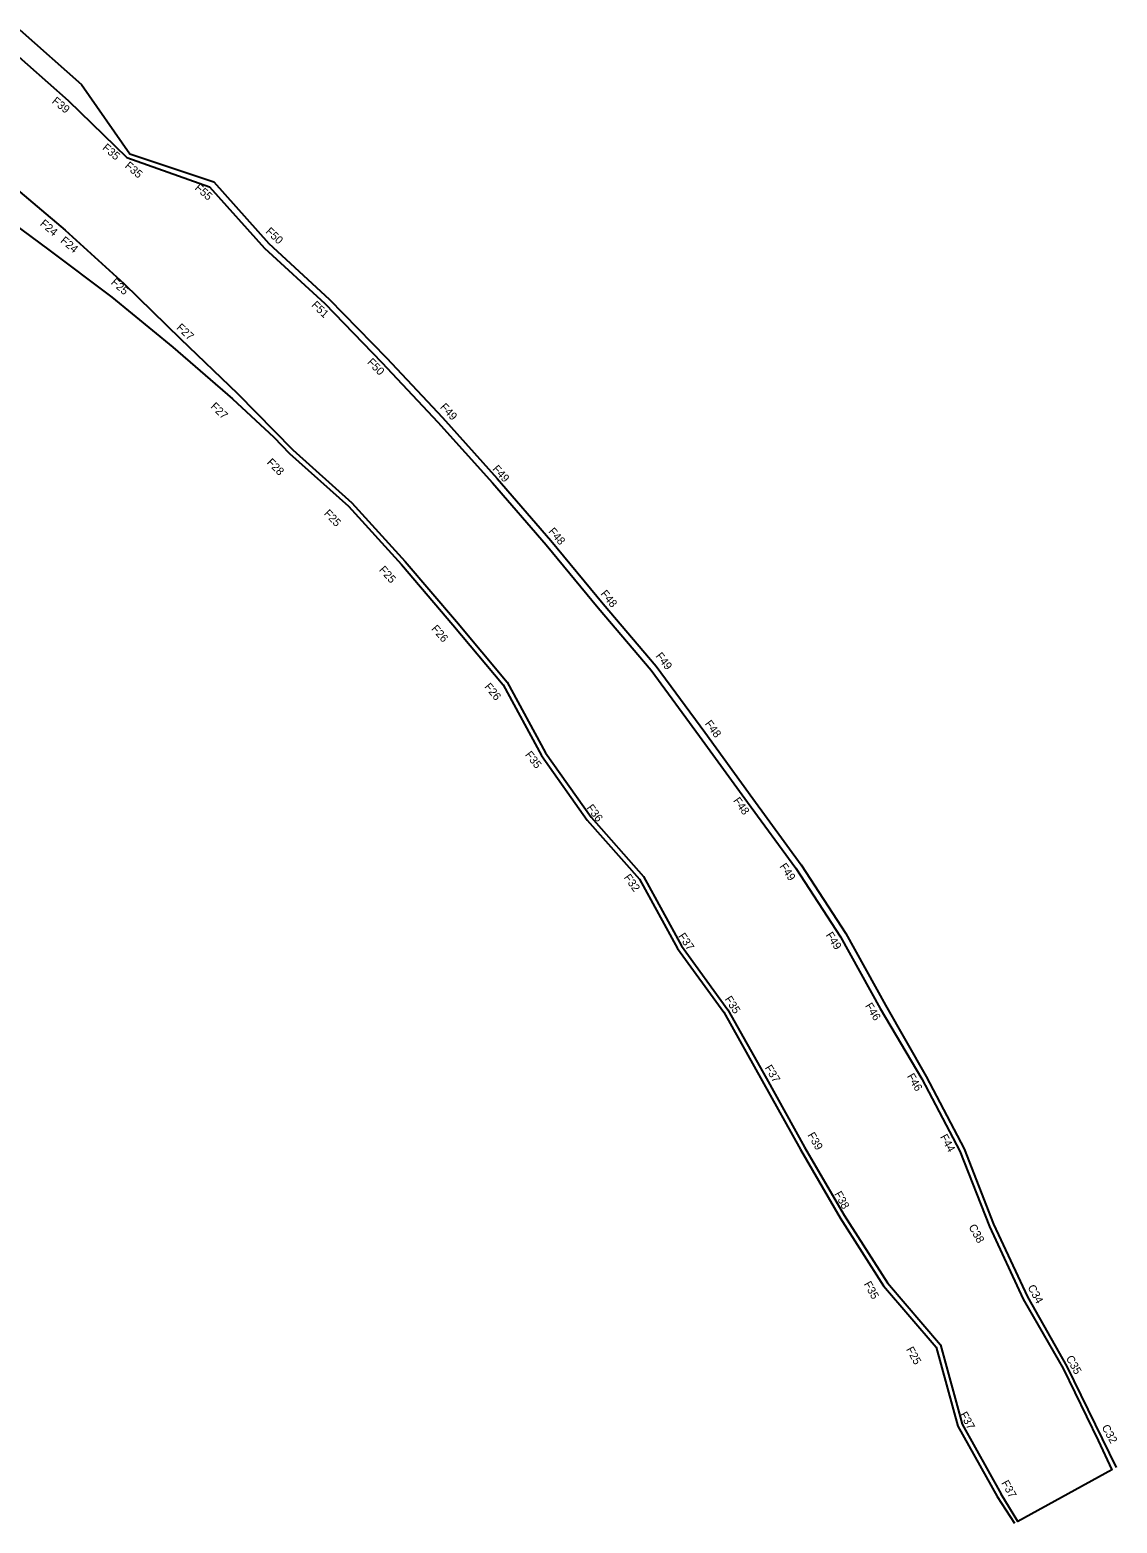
# Model space of a CAD drawing. Extents: x 2165700 to 2171741, y 206405 to 209505.
# Drawn here: x 2171061 to 2171741, y 206405 to 207338 of the extents above; entities that cross this region are included whole.
import ezdxf

# ---------------------------------------------------------------- set-up
doc = ezdxf.new("R2010")
doc.units = 0
for name, color, linetype in [('RD_PD_CstnLmt', 7, 'Continuous'), ('RD_PD_DR_ErosCtrl', 7, 'Continuous'), ('RD_PD_TX_CstnLmt', 7, 'Continuous')]:
    doc.layers.add(name, color=color, linetype=linetype)

msp = doc.modelspace()

# ---------------------------------------------------------------- linework, layer by layer
at = {"layer": 'RD_PD_CstnLmt'}
for points in [[(2171047.22, 207327.63), (2171085.37, 207293.75), (2171121.88, 207258.11), (2171173.6, 207239.9), (2171207.98, 207201.6), (2171245.57, 207166.91), (2171281.22, 207130.23), (2171316.21, 207092.95), (2171350.42, 207054.97), (2171383.88, 207016.35), (2171416.38, 206976.93), (2171449.56, 206938.03), (2171479.81, 206896.82), (2171509.79, 206855.45), (2171540.01, 206814.21), (2171567.81, 206771.31), (2171592.61, 206726.57), (2171618.69, 206682.69), (2171642.4, 206637.48), (2171660.83, 206590.52), (2171682.04, 206545.12), (2171706.99, 206501.78), (2171728.85, 206456.71), (2171737.27, 206438.53), (2171678.59, 206406.09), (2171668.26, 206423.23)], [(2171045.8, 207244.75), (2171083.48, 207212.71), (2171120.08, 207179.45), (2171155.48, 207144.95), (2171191.18, 207110.83), (2171225.73, 207075.56), (2171262.59, 207042.48), (2171295.84, 207005.89), (2171327.95, 206968.3), (2171359.65, 206930.39), (2171383.54, 206886.34), (2171412, 206846.17), (2171444.72, 206809.11), (2171468.47, 206765.68), (2171497.45, 206725.88), (2171521.54, 206682.93), (2171545.4, 206639.95), (2171570.09, 206597.48), (2171597.08, 206555.28), (2171630.29, 206516.51), (2171643.89, 206466.89), (2171668.26, 206423.23)]]:
    msp.add_lwpolyline(points, dxfattribs=at)
at = {"layer": 'RD_PD_DR_ErosCtrl'}
msp.add_line((2171665.64, 206421.77), (2171676.57, 206405.16), dxfattribs=at)
for points in [[(2171055.16, 207337.93), (2171093.53, 207303.87), (2171123.81, 207260.4), (2171176.25, 207242.9), (2171210.7, 207204.53), (2171248.36, 207169.78), (2171284.07, 207133.03), (2171319.12, 207095.69), (2171353.39, 207057.65), (2171386.91, 207018.96), (2171419.47, 206979.46), (2171452.71, 206940.5), (2171483.01, 206899.22), (2171513.05, 206857.77), (2171543.32, 206816.46), (2171571.17, 206773.48), (2171596.02, 206728.66), (2171621.28, 206684.2), (2171645.01, 206638.92), (2171663.46, 206591.98), (2171684.66, 206546.57), (2171684.66, 206546.57), (2171709.21, 206503.01), (2171739.96, 206439.85)], [(2171033.68, 207229.74), (2171073.21, 207200.56), (2171112.57, 207170.97), (2171150.67, 207139.76), (2171187.87, 207107.43), (2171187.87, 207107.43), (2171213.84, 207083.42)], [(2171213.84, 207083.42), (2171223.65, 207073.4), (2171260.47, 207040.35), (2171293.59, 207003.91), (2171325.66, 206966.37), (2171357.15, 206928.7), (2171380.99, 206884.76), (2171409.64, 206844.31), (2171442.25, 206807.38), (2171465.93, 206764.07), (2171494.92, 206724.26), (2171518.92, 206681.47), (2171542.79, 206638.47), (2171567.53, 206595.92), (2171594.67, 206553.49), (2171627.57, 206515.06), (2171641.1, 206465.75), (2171665.64, 206421.77)]]:
    msp.add_lwpolyline(points, dxfattribs=at)

# ---------------------------------------------------------------- texts
at = {"layer": 'RD_PD_TX_CstnLmt'}
for s, rotation, p in [('F39', 321.08168, (2171074.79, 207292.65)), ('F35', 319.77951, (2171106.27, 207263.6)), ('F35', 319.77951, (2171120.34, 207252.32)), ('F55', 318.47733, (2171164.09, 207238.66)), ('F24', 319.77951, (2171067.3, 207216.2)), ('F24', 319.77951, (2171080.07, 207205.6)), ('F50', 317.17515, (2171208.27, 207211.45)), ('F25', 318.47733, (2171111.7, 207179.61)), ('F51', 315.87298, (2171236.93, 207165.6)), ('F27', 317.17515, (2171152.57, 207151.41)), ('F50', 314.5708, (2171271.77, 207129.9)), ('F27', 315.87298, (2171173.86, 207102.21)), ('F49', 313.26862, (2171317.33, 207101.95)), ('F28', 314.5708, (2171209.08, 207067.35)), ('F49', 311.96645, (2171350.06, 207063.41)), ('F25', 313.26862, (2171244.76, 207035.52)), ('F48', 310.66427, (2171385.04, 207024.43)), ('F25', 311.96645, (2171279.19, 207000.38)), ('F48', 309.36209, (2171417.62, 206985.54)), ('F26', 310.66427, (2171311.91, 206963.63)), ('F49', 308.05992, (2171452.07, 206946.7)), ('F26', 309.36209, (2171345.05, 206927.46)), ('F48', 306.75774, (2171482.83, 206904.47)), ('F35', 308.05992, (2171370.51, 206885.04)), ('F36', 306.75774, (2171408.9, 206851.89)), ('F48', 305.45556, (2171500.58, 206856.43)), ('F49', 304.15339, (2171529.55, 206815.37)), ('F32', 305.45556, (2171432.24, 206808.44)), ('F37', 304.15339, (2171466.23, 206771.8)), ('F49', 302.85121, (2171558.41, 206772.49)), ('F35', 302.85121, (2171495.25, 206732.49)), ('F46', 301.54903, (2171583.02, 206728.33)), ('F37', 301.54903, (2171520.26, 206689.56)), ('F46', 300.24685, (2171609.19, 206684.35)), ('F39', 300.24685, (2171547.04, 206647.56)), ('F44', 298.94468, (2171629.87, 206646.45)), ('F38', 298.94468, (2171563.79, 206610.84)), ('C38', 298.938, (2171647.7, 206590.24)), ('F35', 298.938, (2171582.24, 206554.57)), ('C34', 298.938, (2171684.56, 206552.47)), ('F25', 298.938, (2171608.68, 206513.72)), ('C35', 298.938, (2171708.5, 206508.26)), ('F37', 298.938, (2171642.18, 206473.09)), ('C32', 298.938, (2171730.84, 206465.08)), ('F37', 298.938, (2171668.17, 206430.3))]:
    msp.add_text(s, height=5, rotation=rotation, dxfattribs=at).set_placement(p)

doc.saveas('drawing.dxf')
